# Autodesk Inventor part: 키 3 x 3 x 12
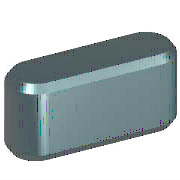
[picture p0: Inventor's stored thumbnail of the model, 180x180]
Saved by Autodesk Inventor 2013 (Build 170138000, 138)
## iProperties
Created: 2012-02
Part Number: 키 3 x 3 x 12
Material: 강철, 연강
Description: 키 및 해당 키홈
Document SubType Name: Modeling
Standard: KS B 1311
Designer: mduedu
Standards Organization: KS
Language: ko-KR
Size Designation: 3 x 3 x 12
Categories: <MemberInstance><Categories><Category DisplayName="샤프트 부품" InternalName="7f7aeb1f-a693-4053-b835-cee3144e0d98" Mnemonic="SHFT"><Category DisplayName="키" Interna
Density: 1 g/cm^3
IsCustomPart: 1
Author: mduedu
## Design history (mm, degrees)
workplane "Work Plane1"
workplane "Work Plane2"
sketch "스케치1"
  geometry: L1 (1.5, 1.5)-(10.5, 1.5); L2 (10.5, -1.5)-(1.5, -1.5); L3 (0, 9.4)-(0, -7.4) reference; L4 (-5, 0)-(30, 0) reference; L5 (12, 0)-(12, 7); A1 r 1.5 centre (1.5, 0) between (1.5, 1.5) and (1.5, -1.5); A2 r 1.5 centre (10.5, 0) between (10.5, -1.5) and (10.5, 1.5)
  constraints: 6 end point, 5 point on circle, 4 tangent, 3 point on line, 2 centre point, 1 horizontal, 1 parallel, 1 perpendicular
  dimensions: "d0" = 1.5 radius of A1 (= 0.5 x PB); "d13" = 1.5 radius of A2 (= 0.5 x PB); "d14" = 12 distance between parallel lines of L5 L3 (= NLG)
extrude "본체1" new body sketch "스케치1" taper "d3" = 0 deg; stored distance "d4" = 10
workplane "Work Plane3"
body "Solid1"
chamfer "모따기1" distance "d8" = 0.25 (= PHH); stored, may be unused: second distance "d9" = 0.25 (= PHH), angle "d15" = 45 deg
other parameters: "d1" = -1.8 (= -PNT), "d2" = 1.2 (= PH - PNT), "NLG" = 12 [user parameter; used in 3 equation terms], "PB" = 3 [user parameter; used in 2 equation terms], "PNT" = 1.8 [user parameter; used in 2 equation terms], "PH" = 3 [user parameter; used in 1 equation term], "PHH" = 0.25 [user parameter; used in 2 equation terms], "d10" = 0, "d16" = 0, "d17" = 0, "d18" = 0, "WDMIN" = 8 [user parameter], "PLB2" = 12 (= NLG) [user parameter], "PLB1" = 12 (= NLG) [user parameter], "RR" = 0.08 [user parameter], "PUEB" = 1.4 [user parameter]
